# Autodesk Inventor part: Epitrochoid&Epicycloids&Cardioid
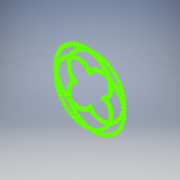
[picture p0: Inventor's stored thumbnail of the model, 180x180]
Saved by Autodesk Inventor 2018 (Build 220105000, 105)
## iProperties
Created: 2008-02
Part Number: Epitrochoid&Epicycloids&Cardioid
Document SubType Name: Modeling
Designer: Autodesk, Inc.
Density: 1 g/cm^3
Material: Generic
Appearance: Default
Author: Autodesk, Inc.
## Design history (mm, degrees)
sketch "Sketch1"
  geometry: 300 further points
  constraints: 300 other
